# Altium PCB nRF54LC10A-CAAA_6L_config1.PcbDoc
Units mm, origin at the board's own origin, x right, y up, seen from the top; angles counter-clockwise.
Board outline 10.2 x 7.5 mm, 6 copper layers (Top Layer, Mid-Layer 1, Mid-Layer 2, Mid-Layer 3, Mid-Layer 4, Bottom Layer), stack 1.69 mm thick; 17 components, 27 nets, 63 pads, 76 vias.
Unrouted connection lines stored in the file: 14.
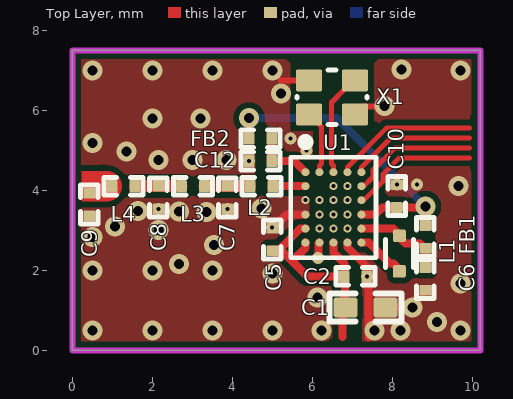
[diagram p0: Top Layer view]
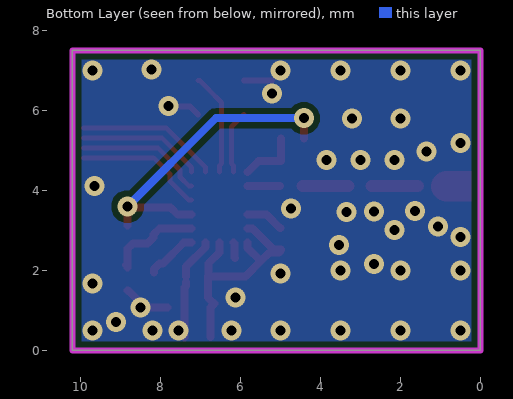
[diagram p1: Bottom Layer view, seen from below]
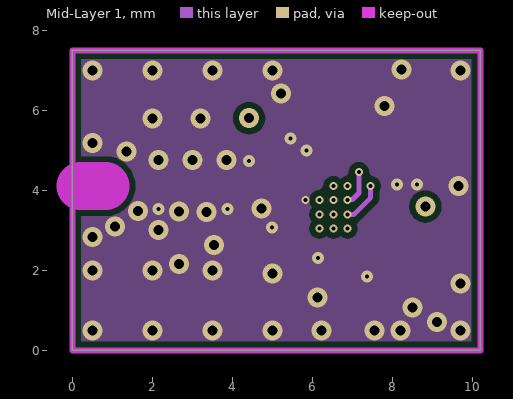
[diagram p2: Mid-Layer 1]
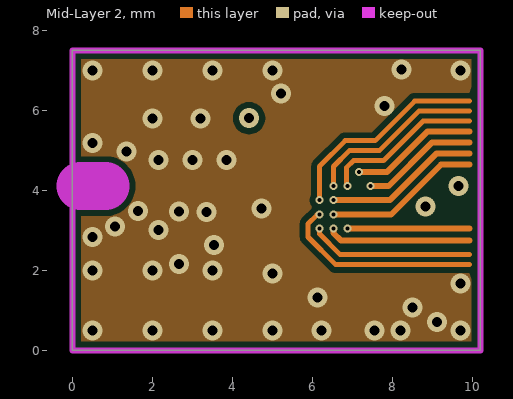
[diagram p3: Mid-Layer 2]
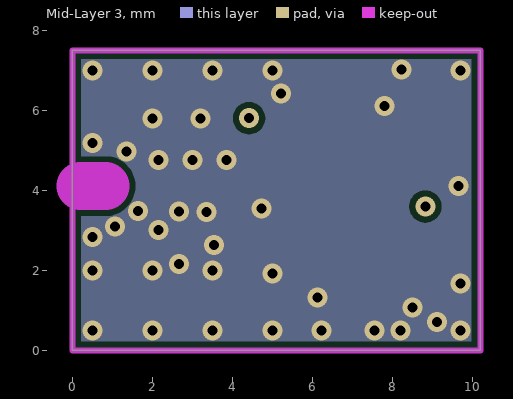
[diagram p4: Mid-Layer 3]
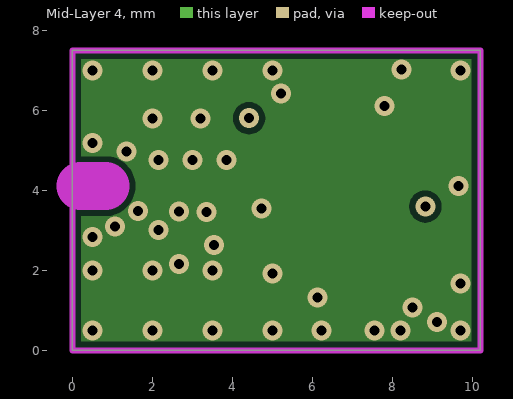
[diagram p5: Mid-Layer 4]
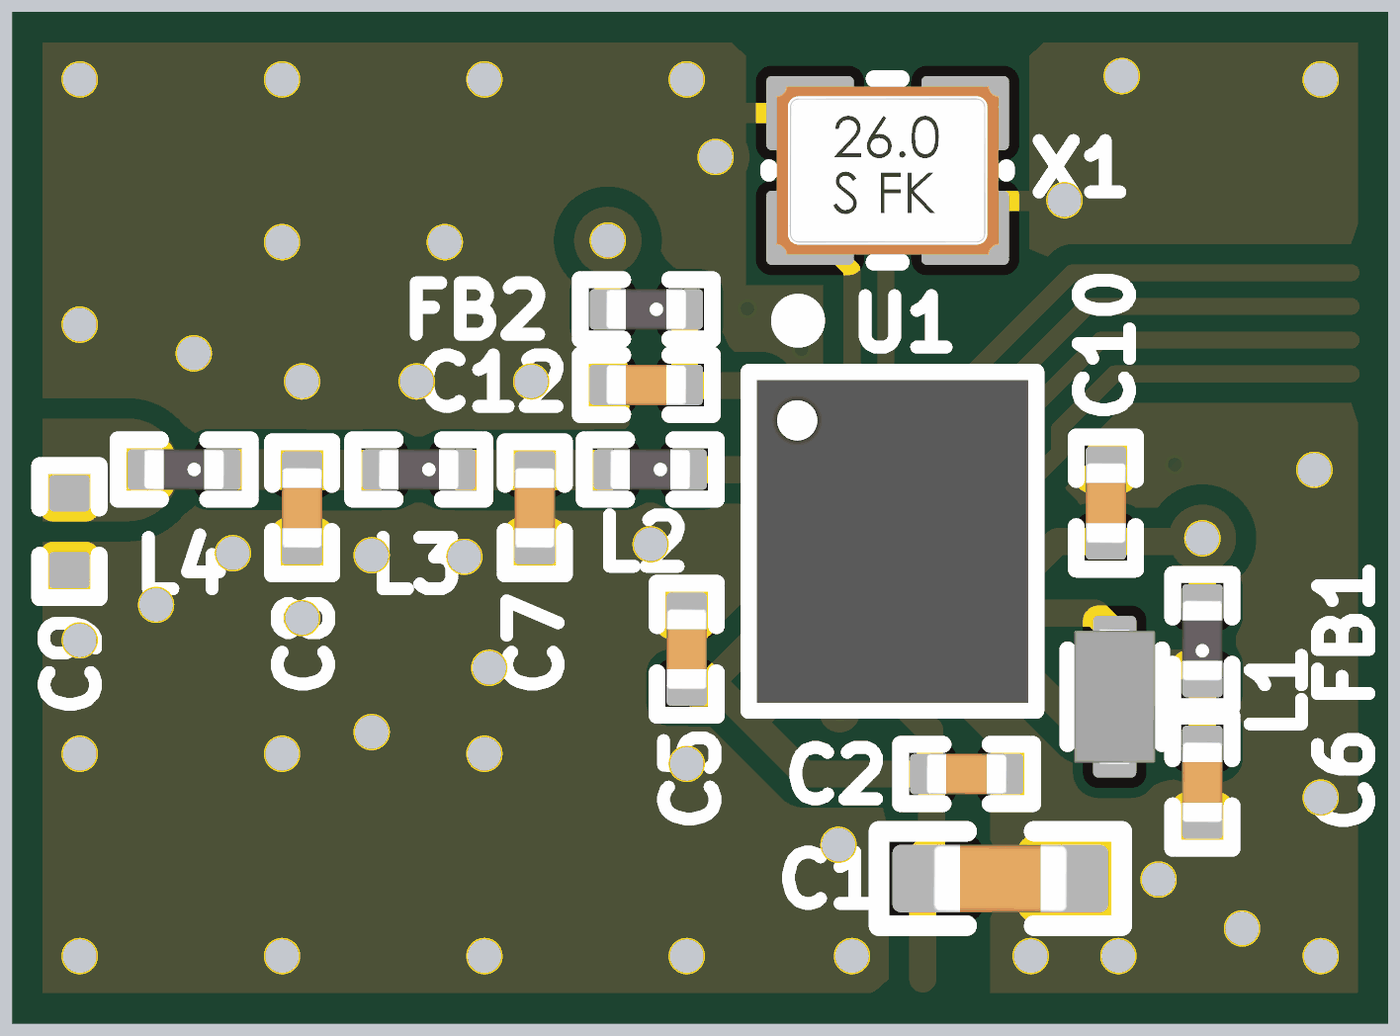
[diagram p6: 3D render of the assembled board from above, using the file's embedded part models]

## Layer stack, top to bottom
Top Solder: solder mask 0.011, Solder Resist, Dk 3.5
Top Layer: signal copper 0.035
Dielectric 1: prepreg 0.07, Dk 4.2
Mid-Layer 1: signal copper 0.035
Dielectric 4: prepreg 0.07, Dk 4.1
Mid-Layer 2: signal copper 0.035
Dielectric 3: core 1.2, Dk 4.6
Mid-Layer 3: signal copper 0.035
Dielectric 5: prepreg 0.07, Dk 4.1
Mid-Layer 4: signal copper 0.035
Dielectric 2: prepreg 0.07, Dk 4.2
Bottom Layer: signal copper 0.035
Bottom Solder: solder mask 0.011, Solder Resist, Dk 3.5

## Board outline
0,0 0,7.5 10.2,7.5 10.2,0

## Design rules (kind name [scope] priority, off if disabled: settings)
Clearance Polygon_ANT [InNet('GND') vs InNet('RF')] p1: gap=0.15 ignorepadtopadclearanceinfootprint=FALSE
Clearance Clearance_Poly [(InNamedPolygon('Top_Layer-GND')) or (InNamedPolygon('Bottom_Layer-GND')) or (InNamedPolygon('Mid_Layer1-GND')) or (InNamedPolygon('Mid_Layer2-GND'))] p2: gap=0.15 ignorepadtopadclearanceinfootprint=FALSE
Clearance Clearance_nRF54 [WithinRoom('nRF54')] p3: gap=0.1 ignorepadtopadclearanceinfootprint=FALSE except(0: Arc-Hole Track-Hole SMDPad-Hole THPad-Hole Via-Hole Fill-Hole Poly-Hole Region-Hole Text-Hole; 0.15: Arc-Poly Arc-Region Track-Poly Track-Region SMDPad-Poly SMDPad-Region THPad-Poly THPad-Region Via-Poly Via-Region Fill-Poly Fill-Region Poly-Poly Poly-Region Region-Region)
Clearance [All] p4: gap=0.125 ignorepadtopadclearanceinfootprint=FALSE
ComponentClearance [All] p1 off: gap=0.254 collisioncheckmode=3 verticalgap=0.254 showdistances=FALSE
FabricationTestPointUsage TestPointUsage [All] p1: valid=0 allowmultiple=FALSE
FabricationTestpoint Testpoint [All] p1: side=3 testpointundercomponent=TRUE minsize=1.016 maxsize=2.54 preferedsize=1.524 minholesize=0 maxholesize=1.016 preferedholesize=0.813 testpointgrid=0.025 allowsidetop=TRUE allowsidebottom=TRUE usegrid=TRUE gridtolerance=0
Height [All] p1 off: minheight=0 maxheight=25.4 prefheight=12.7
HoleSize [All] p1: absolutevalues=TRUE maxlimit=4 minlimit=0.1 maxpercent=80.000 minpercent=20.000
HoleToHoleClearance [IsThruVia vs IsThruVia] p1: gap=0.36 allowstackedmicrovias=TRUE
MinimumAnnularRing [All] p1 off: minimumring=0.152
PlaneClearance [All] p1: clearance=0.2
PolygonConnect Component_direct [All] p1: connectstyle=Direct reliefconductorwidth=0.254 reliefentries=4 polygonreliefangle="90 Angle" airgapwidth=0.254
PolygonConnect "Via GND" [isVia and innet('GND')] p2: connectstyle=Direct reliefconductorwidth=0.254 reliefentries=4 polygonreliefangle="90 Angle" airgapwidth=0.254
PolygonConnect [All] p3: thpad.connectstyle=Relief thpad.reliefconductorwidth=0.254 thpad.reliefentries=4 thpad.polygonreliefangle="90 Angle" thpad.airgapwidth=0.15 smdpad.connectstyle=Relief smdpad.reliefconductorwidth=0.25 smdpad.reliefentries=4 smdpad.polygonreliefangle="90 Angle" smdpad.airgapwidth=0.15 via.connectstyle=Direct via.reliefconductorwidth=0.254 via.reliefentries=4 via.polygonreliefangle="90 Angle" via.airgapwidth=0.25
RoutingVias [All] p1: holewidth=0.2 width=0.4 viastyle="Through Hole" minholewidth=0.1 minwidth=0.2 maxholewidth=1 maxwidth=2 useviatemplates=TRUE viatemplateguid#1={5C31B0A3-9274-4A8C-AAD4-E2B2741298D6} viatemplateguid#2={C8464F81-CA02-4378-B3B7-72CF0372187D} viatemplatename#1=v20h10m0 viatemplatename#2=v30h10m0
SilkToSolderMaskClearance SilkscreenOverComponentPads [IsPad] p1: minsilkscreentomaskgap=0.254 clearancetoexposedcopper=TRUE
SolderMaskExpansion SolderMaskExpansion_via [IsVia] p1: expansion=0.102 istentingtop=TRUE
SolderMaskExpansion [All] p2: expansion=0.076 istentingtop=FALSE
SupplyNets "Schematic Supply Nets_1" [InNet('VDD:nRF')] p1: voltage=0.000
SupplyNets "Schematic Supply Nets" [InNet('GND')] p2: voltage=0.000
Width [All] p1: maxlimit=3 minlimit=0.125 preferedwidth=0.15
22 further rules are at their usual default settings.

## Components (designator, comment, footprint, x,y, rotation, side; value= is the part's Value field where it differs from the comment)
C1 "10µF" CAPC1005X04L 7.325,1.075 r180 top
C2 "100nF" CAPC0603X03L_C 7.075,1.85 r0 top
C5 "100nF" CAPC0603X03L_C 5,2.775 r90 top
C6 "4.7µF" CAPC0603X03L_C 8.823,1.789 r90 top
C7 "1.5pF" CAPC0603X03L_C 3.874,3.823 r270 top
C8 "1.2pF" CAPC0603X03L_C 2.149,3.823 r270 top
C9 "N.C." CAPC0603X03L_C_NC 0.424,3.647 r90 top
C10 "2.2µF" CAPC0603X03L_C 8.108,3.859 r270 top
C12 "2.2µF" CAPC0603X03L_C 4.7,4.735 r0 top
FB1 "120R/0.2A" INDC0603X03L_C 8.823,2.839 r90 top
FB2 "120R/0.2A" INDC0603X03L_C 4.7,5.296 r180 top
L1 "4.7µH" INDDFN10X06X08L31X32L 8.173,2.423 r90 top
L2 "3.3nH" INDC0603X03L_C 4.73,4.108 r180 top
L3 "5.1nH" INDC0603X03L_C 3.014,4.108 r180 top
L4 "3.3nH" INDC0603X03L_C 1.274,4.108 r180 top
U1 "nRF54LC10A-CAAA" BGA29CP35_5X6_239X201X45B20 6.525,3.575 r0 top
X1 "32MHz" BT-XTAL_1612 6.489,6.325 r0 top

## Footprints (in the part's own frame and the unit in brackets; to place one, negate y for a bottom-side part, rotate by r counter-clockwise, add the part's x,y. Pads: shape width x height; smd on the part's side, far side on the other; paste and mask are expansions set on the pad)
BGA29CP35_5X6_239X201X45B20 [mm] "Ball Grid Array (BGA) Collapsing, 0.35 mm pitch, rect.; 29 pin, 2.393 mm L X 2.012 mm W X 0.45 mm H body"
  round 0.2 smd paste+0 mask+0.025: A1(-0.7,0.88) A2(-0.35,0.88) A3(0,0.88) A4(0.35,0.88) A5(0.7,0.88) B1(-0.7,0.53) B3(0,0.53) B4(0.35,0.53) B5(0.7,0.53) C1(-0.7,0.18) C2(-0.35,0.18) C3(0,0.18) C4(0.35,0.18) C5(0.7,0.18) D1(-0.7,-0.18) D2(-0.35,-0.18) D3(0,-0.18) D4(0.35,-0.18) D5(0.7,-0.18) E1(-0.7,-0.53) E2(-0.35,-0.53) E3(0,-0.53) E4(0.35,-0.53) E5(0.7,-0.53) F1(-0.7,-0.88) F2(-0.35,-0.88) F3(0,-0.88) F4(0.35,-0.88) F5(0.7,-0.88)
  silkscreen extent -1.07,-1.26 1.07,1.74, body extent -1.01,-1.2 1.01,1.2, height 0.45
BT-XTAL_1612 [mm] "Crystal 1.6 x 1.2 mm"
  rrect15% 0.65x0.55 smd: 1(-0.575,-0.425) 2(0.575,-0.425) 3(0.575,0.425) 4(-0.575,0.425)
  silkscreen extent -0.88,-0.68 0.88,0.68, body extent -0.83,-0.63 0.83,0.63, height 0.41
CAPC0603X03L_C [mm] "Chip Capacitor, 2-Leads, Body 0.6x0.3mm, IPC High Density"
  rrect25% 0.27x0.3 smd: 1(-0.285,0) 2(0.285,0)
  silkscreen extent -0.49,-0.22 0.49,0.22, body extent -0.3,-0.15 0.3,0.15, height 0.3
CAPC0603X03L_C_NC [mm] "Chip Capacitor, 2-Leads, Body 0.6x0.3mm, IPC High Density"
  rrect25% 0.27x0.3 smd: 1(-0.285,0) 2(0.285,0)
  silkscreen extent -0.49,-0.22 0.49,0.22
CAPC1005X04L [mm] "Chip Capacitor, 2-Leads, Body 1.0x0.5mm, IPC High Density"
  rrect25% 0.6x0.5 smd: 1(-0.5,0) 2(0.5,0)
  silkscreen extent -0.9,-0.35 0.9,0.35, body extent -0.5,-0.25 0.5,0.25, height 0.5
INDC0603X03L_C [mm] "Chip Inductor, 2-Leads, Body 0.6x0.3mm, IPC High Density"
  rrect25% 0.27x0.3 smd: 1(-0.285,0) 2(0.285,0)
  silkscreen extent -0.49,-0.22 0.49,0.22, body extent -0.3,-0.15 0.3,0.15, height 0.3
INDDFN10X06X08L31X32L [mm] "Inductor Dula Flat Package, 2-Leads, Body 1.0x0.6mm, IPC High Density"
  rrect25% 0.31x0.32 smd mask+0.076: 1(-0.445,0) 2(0.445,0)
  silkscreen extent -0.35,-0.35 0.35,0.35, body extent -0.5,-0.3 0.5,0.3, height 0.79

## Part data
C1: library part C0402-10µF-6.3V-X6S, "Capacitor, X6S, ±20%, 6.3V", Manufacturer=N.A., Part number NEMS=100200478
C2 C5: library part C0201-100n-10V-X7R, "Capacitor, X7R, ±10%, 10V", Manufacturer=N.A., Part number NEMS=100200469
C6: library part C0201-4.7µ-6V3-X5R-GRM035R60J475ME15J, "Capacitor, Ceramic, X5R, ±20%, 6.3V", Manufacturer=Murata, Manufacturer Part Number=GRM035R60J475ME15J, Part number IPS=N.A., Part number NEMS=100200685, Supplier Part Number 1=490-GRM035R60J475ME15JDKR-ND
C7: library part C0201-1.5p_RF, "RF Chip Cap 0201", Manufacturer=N.A., Part number NEMS=100200087
C8: library part C0201-1.2p-HQ-Murata, "Capacitor, NP0, ±0.05pF, 50V", Manufacturer=Murata, Manufacturer Part Number=GJM0335C1H1R2WB01D, Part number IPS=N.A., Part number NEMS=100200457, Supplier Part Number 1=490-GJM0335C1H1R2WB01DCT-ND
C9: library part C0201-N.C., "Not mounted", Manufacturer=N.A., Part number NEMS=100200001
C10 C12: library part C0201-2µ2-2.5V-X6T-GRM033D80E225ME47D, "Capacitor, Ceramic, 2.2µF 2.5V X6T 0201,±20%", Manufacturer=Murata, Manufacturer Part Number=GRM033D80E225ME47D, Part number IPS=N.A., Part number NEMS=100200527, Supplier Part Number 1=81-GRM033D80E225ME7D
FB1 FB2: library part FB0201-120R@100M-200mA-BLM03AG121SN1D, "Ferrite Bead, 120 Ohm @ 100MHz, 200mA, 500 mOhm Max", Manufacturer=Murata, Manufacturer Part Number=BLM03AG121SN1D, Part number IPS=N.A., Part number NEMS=100300419, Supplier Part Number 1=490-5622-1-ND
L1: library part L0402-4µ7-PLEA67BCA4R7M-1PT00, "Inductor, 300mA, ±20%, 1.08R", Manufacturer="TDK Corporation", Manufacturer Part Number=PLEA67BCA4R7M-1PT00, Part number IPS=N.A., Part number NEMS=100300441, Supplier Part Number 1=445-PLEA67BCA4R7M-1PT00TR-ND
L2 L4: library part L0201-3n3-HQ-Murata, "Inductor, 500mA, ±0.1ｎH, 170mOhm", Manufacturer=Murata, Manufacturer Part Number=LQP03HQ3N3B02, Part number IPS=N.A., Part number NEMS=100300220, Supplier Part Number 1=490-13921-1-ND
L3: library part L0201-5n1-HQ-Murata, "Inductor, 400mA, ±3%, 250mOhm", Manufacturer=Murata, Manufacturer Part Number=LQP03HQ5N1H02, Part number IPS=N.A., Part number NEMS=100300235, Supplier Part Number 1=490-13945-1-ND
U1: "Multi-protocol Bluetooth Low Energy, IEEE 802.15.4 and 2.4GHz proprietary Wireless MCU", Manufacturer="Nordic Semiconductor", Part number IPS=N.A., Part number NEMS=102000467
X1: library part XTAL_SMD1612_32MHz_8pF_Kyocera, "XTAL SMD 1612, 32MHz, Cl=8pF, Tot: ±40ppm, Aging: ±1ppm/year", Manufacturer=Kyocera, Manufacturer Part Number=CX1612DB32000D0WZRC3, Part number IPS=N.A., Part number NEMS=101600029

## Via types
v1: diameter 0.5, hole 0.25, Top Layer to Bottom Layer, tented both sides, 43 vias
v2: diameter 0.2, hole 0.1, Top Layer to Mid-Layer 1, tented top, 12 vias
v3: diameter 0.2, hole 0.1, Mid-Layer 1 to Mid-Layer 2, 11 vias
v4: diameter 0.3, hole 0.1, Top Layer to Mid-Layer 1, tented top, 10 vias

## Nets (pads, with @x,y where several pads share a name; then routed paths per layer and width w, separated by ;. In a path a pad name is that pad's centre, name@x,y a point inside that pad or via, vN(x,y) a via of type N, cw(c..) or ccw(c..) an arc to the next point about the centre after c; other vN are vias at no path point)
ANT: L2.1 U1.B1 | length 0.8
  Top Layer w0.2: L2.1@5.014,4.105 U1.B1
DCC: L1.1 U1.F5 | length 1.3
  Top Layer w0.2: U1.F5@7.223,2.693 7.418,2.693 7.938,2.173 8.023,2.173 8.163,2.033 L1.1@8.163,1.948
DECA: C10.2 FB1.2 FB2.2 U1.D5 | length 8
  Top Layer w0.2: FB2.2 v1@4.415,5.8 ; U1.D5@7.223,3.393 7.567,3.393 7.748,3.574 C10.2 8.799,3.574 v1(8.823,3.598) FB1.2
  Bottom Layer w0.2: v1(4.415,5.805) 6.615,5.805 v1(8.823,3.598)
DECD: C6.2 FB1.1 L1.2 U1.E5 | length 2.4
  Top Layer w0.15: C6.2 C6.2@8.883,2.134
  Top Layer w0.2: U1.E5@7.223,3.043 8.028,3.043 8.173,2.898 8.173,2.823 8.323,2.673 8.689,2.673 8.808,2.554 FB1.1 C6.2
DECRF: C12.2 FB2.1 U1.A1 | length 1.4
  Top Layer w0.2: C12.2 FB2.1 ; C12.2@5.06,4.73 5.55,4.73 U1.A1
GND: C1.1 C2.2 C5.2 C6.1 C7.2 C8.2 C9.1 C10.1 C12.1 U1.C1 U1.D1 U1.F2 U1.F4 X1.2 X1.4 | length 6.6
  Top Layer w0.15: 5.214,6.75 X1.4 ; X1.2 7.264,6.1 v1@7.795,6.1
  Top Layer w0.2: C5.2 5.015,3.06 5.35,3.395 U1.D1 U1.D1@5.827,3.397 ; v4(6.134,2.309) 6.153,2.328 6.153,2.673 U1.F2 ; U1.F4 6.875,2.581 7.36,2.096 v4(7.36,1.85) ; C2.2@7.36,1.707 7.36,1.615 7.4,1.575 v1@7.4,0.325 ; C1.1@7.823,1.073 7.825,1.07 8.495,1.07 v1(8.498,1.068) 8.555,1.125 8.555,1.251 8.808,1.504 C6.1 ; C1.1 C1.1@7.827,1.072
  other v1: 0.5,0.5 2,0.5 3.5,0.5 5,0.5 6.225,0.5 7.55,0.5 8.2,0.5 9.7,0.5 9.117,0.705 6.125,1.325 9.7,1.675 5,1.925 0.5,2 2,2 3.5,2 2.664,2.161 3.536,2.637 0.5,2.841 2.149,3.006 1.066,3.104 2.664,3.472 3.351,3.461 1.635,3.487 4.732,3.553 9.653,4.106 2.149,4.761 2.998,4.761 3.847,4.761 1.345,4.969 0.5,5.182 2,5.794 3.206,5.794 7.8,6.105 5.214,6.425 0.5,7 2,7 3.5,7 5,7 9.7,7 8.225,7.025
  other v2: 5.825,3.755
  other v4: 4.993,3.067 2.149,3.538 3.874,3.538 8.108,4.144 8.618,4.144 4.415,4.735 5.85,5 5.45,5.3
NetC7_1: C7.1 L2.2 L3.1 | length 1.1
  Top Layer w0.3: L3.1@3.298,4.105 L2.2@4.444,4.105
NetC8_1: C8.1 L3.2 L4.1 | length 1.2
  Top Layer w0.3: L4.1 C8.1 ; C8.1@2.149,4.105 L3.2@2.728,4.105
NRESET: U1.C2 | length 5.3
  Mid-Layer 2 w0.125: v2(6.175,3.755) 6.175,4.601 6.818,5.245 7.57,5.245 8.556,6.231 9.925,6.231
  other v3: 6.175,3.755
P1.00/AIN0: U1.E3 | length 3.6
  Mid-Layer 2 w0.15: v2(6.525,3.045) 6.525,2.935 6.716,2.744 9.925,2.744
  other v3: 6.525,3.045
P1.01/AIN1: U1.C3 | length 3.9
  Mid-Layer 2 w0.15: v3(6.525,3.755) 7.936,3.755 9.1,4.919 9.925,4.919
  other v2: 6.525,3.755
P1.02/AIN2: U1.D3 | length 3.9
  Mid-Layer 2 w0.15: v3(6.525,3.395) 7.965,3.395 9.214,4.644 9.925,4.644
  other v2: 6.525,3.395
P1.03/AIN3: U1.A4 | length 3.6
  Top Layer w0.125: U1.A4 6.875,4.582 7.86,5.567 9.925,5.567
P1.05: U1.B4 | length 4
  Mid-Layer 2 w0.125: v2(6.875,4.105) 6.857,4.123 6.857,4.576 7.025,4.745 7.777,4.745 8.764,5.731 9.925,5.731
  other v3: 6.875,4.105
P1.07/AIN4: U1.C4 | length 4.1
  Mid-Layer 1 w0.125: v2(6.875,3.755) 6.894,3.774 7,3.774 7.163,3.936 7.163,4.45 v3@7.17,4.457
  Mid-Layer 2 w0.15: v3(7.163,4.457) 7.861,4.457 8.872,5.469 9.925,5.469
P1.09: U1.B3 | length 4.5
  Mid-Layer 2 w0.125: v2(6.525,4.105) 6.525,4.598 6.922,4.995 7.673,4.995 8.66,5.981 9.925,5.981
  other v3: 6.525,4.105
P1.10/AIN5: U1.A5 | length 3.1
  Top Layer w0.125: U1.A5 7.225,4.578 7.964,5.317 9.925,5.317
P1.11/AIN6: U1.D4 | length 4
  Mid-Layer 1 w0.125: v2(6.875,3.395) 7.032,3.395 7.455,3.819 v3(7.455,4.108)
  Mid-Layer 2 w0.15: v3(7.455,4.108) 7.9,4.108 8.986,5.194 9.925,5.194
P1.12/AIN7: U1.E4 | length 3
  Mid-Layer 2 w0.15: v3@6.889,3.045 9.925,3.045
  other v2: 6.875,3.045
  other v3: 6.875,3.045
P1.13/XL1: U1.B5 | length 3.2
  Top Layer w0.125: U1.B5 7.282,4.105 7.513,4.336 7.513,4.512 8.067,5.067 9.925,5.067
P1.14/XL2: U1.C5 | length 3.2
  Top Layer w0.125: U1.C5 7.285,3.755 7.763,4.232 7.763,4.408 8.171,4.817 8.212,4.817 8.385,4.817 9.925,4.817
RF: C9.2 L4.2 | length 0.2
  Top Layer w0.762: 0.7,4.105 L4.2@0.857,4.105
SWDCLK: U1.D2 | length 5
  Mid-Layer 2 w0.125: v3(6.173,3.395) 6.118,3.395 5.887,3.164 5.887,2.838 6.581,2.144 9.925,2.144
  other v2: 6.175,3.395
SWDIO: U1.E2 | length 4.1
  Mid-Layer 2 w0.125: v2(6.175,3.045) 6.175,2.914 6.695,2.394 9.925,2.394
  other v3: 6.175,3.045
VDD:nRF: C1.2 C2.1 C5.1 U1.E1 U1.F1 U1.F3 | length 6.3
  Top Layer w0.2: C5.1@4.985,2.525 5.175,2.525 5.695,3.045 U1.E1 ; C5.1 5.038,2.452 5.273,2.452 5.493,2.232 ; U1.F1 5.825,2.565 5.493,2.232 ; U1.F3 6.525,2.45 6.803,2.172 C2.1@6.803,1.862 ; 6.75,0.33 6.75,1.075 6.65,1.175 6.665,1.175 6.815,1.325 C2.1@6.815,1.85 ; C2.1@6.786,1.846 C2.1 5.875,1.85 5.493,2.232
XC1: U1.A2 X1.1 | length 1.6
  Top Layer w0.125: X1.1 6.225,5.589 6.225,4.667 6.175,4.617 U1.A2
XC2: U1.A3 X1.3 | length 2.6
  Top Layer w0.125: U1.A3 6.525,4.617 6.475,4.667 6.475,6.2 6.802,6.527 6.802,6.537 7.014,6.75 X1.3

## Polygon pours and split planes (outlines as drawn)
GND on Mid-Layer 4 "Mid_Layer2-GND" (solid, pour order 3): 0,7.48 0,0 10.2,0 10.2,7.48 7.964,7.48
GND on Mid-Layer 3 "Top_Layer-GND" (solid, remove dead copper, pour order 12): 0,0 10.2,0 10.2,7.475 0,7.475
GND on Mid-Layer 1 "Mid_Layer1-GND" (solid, pour order 11): 0,7.48 0,0 10.2,0 10.2,7.48 7.964,7.48
GND on Mid-Layer 2 "Top_Layer-GND" (solid, remove dead copper, pour order 10): 0,0 10.2,0 10.2,7.475 0,7.475
GND on Bottom Layer "Bottom_Layer-GND" (solid, pour order 2): 0,7.5 10.2,7.5 10.2,0 0,0
GND on Top Layer "Top_Layer-GND" (solid, remove dead copper, pour order 13): 0,0 10.2,0 10.2,7.475 0,7.475

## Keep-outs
Mid-Layer 1:
  lines w1.2: 0.2,4.108 0.831,4.108
Mid-Layer 4:
  lines w1.2: 0.2,4.108 0.831,4.108
Mid-Layer 2:
  lines w1.2: 0.2,4.108 0.831,4.108
Mid-Layer 3:
  lines w1.2: 0.2,4.108 0.831,4.108
Keep-Out Layer:
  the board outline again, w0.15

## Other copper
Top Layer:
  region net RF: 0.7,4.486 0.225,4.486 0.225,3.724 0.7,3.724
  pour cut-out: 5.439,7.175 7.539,7.175 7.539,5.475 5.439,5.475
  pour cut-out: 5.925,3.85 5.925,3.325 6.05,3.325 6.05,3.6 6.05,3.85
  pour cut-out: 4.576,5.577 4.576,4.386 4.701,4.386 4.701,4.661 4.701,5.577
  pour cut-out: 5.925,3.832 5.925,3.308 6.05,3.308 6.05,3.582 6.05,3.832
  pour cut-out: 6.95,0.2 6.95,2.28 7.25,2.28 7.25,0.2
Mid-Layer 2:
  pour cut-out: 9.305,4.494 9.283,4.471 9.283,3.725 10.048,3.725 10.13,3.807 10.13,4.563

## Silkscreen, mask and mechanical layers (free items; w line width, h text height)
Mechanical 1:
  the board outline again, w0.15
